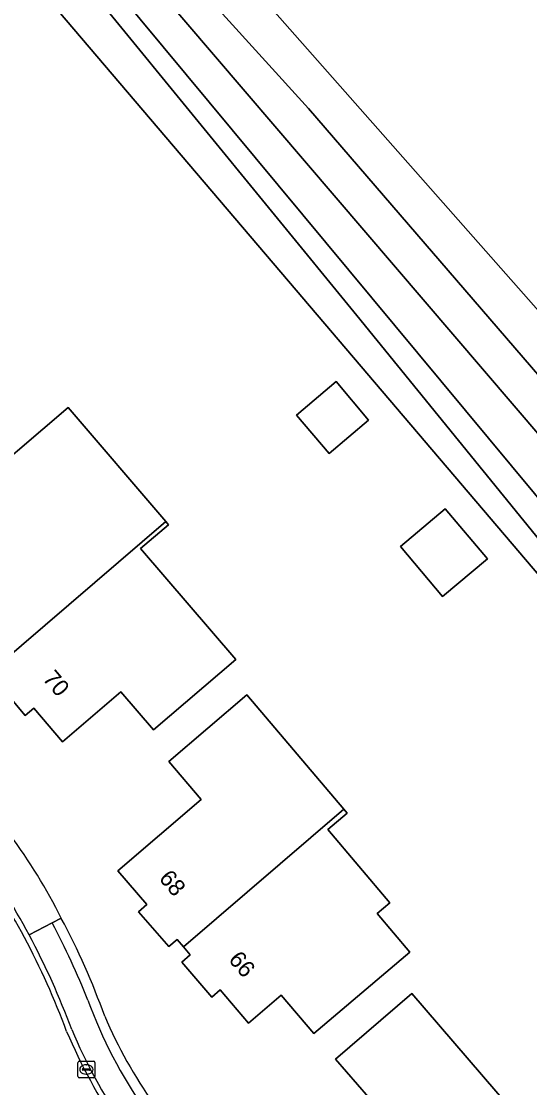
# Model space of a CAD drawing. Extents: x 164148 to 165261, y 382513 to 383432.
# Drawn here: x 164586 to 164616.4, y 383245.5 to 383309.2 of the extents above; entities that cross this region are included whole.
import ezdxf

# ---------------------------------------------------------------- set-up
doc = ezdxf.new("R2010")
doc.units = 0
for name, color, linetype in [('IMGEO_Erf', 7, 'Continuous'), ('IMGEO_Groenvoorziening', 7, 'Continuous'), ('IMGEO_Hek', 7, 'Continuous'), ('IMGEO_Kolk', 7, 'Continuous'), ('IMGEO_Oever', 7, 'Continuous'), ('IMGEO_Pand', 7, 'Continuous'), ('IMGEO_Pand_nummerreeks', 7, 'Continuous'), ('IMGEO_Parkeervlak_open', 7, 'Continuous'), ('IMGEO_Rijbaan_lokaal_open', 7, 'Continuous'), ('IMGEO_Voetpad_open', 7, 'Continuous'), ('IMGEO_Waterloop', 7, 'Continuous')]:
    doc.layers.add(name, color=color, linetype=linetype)

msp = doc.modelspace()

# ---------------------------------------------------------------- linework, layer by layer
at = {"layer": 'IMGEO_Erf'}
for points in [[(164601.938, 383293.634), (164580.845, 383318.389), (164573.491, 383327.02), (164568.932, 383331.938), (164563.693, 383332.71), (164545.833, 383335.341), (164545.779, 383334.975), (164544.24, 383324.617), (164544.174, 383323.62), (164543.739, 383320.602), (164543.186, 383316.778)], [(164608.532, 383221.856), (164626.392, 383219.249), (164626.412, 383219.679), (164643.122, 383217.367), (164643.541, 383216.874), (164670.853, 383212.753), (164601.938, 383293.634)]]:
    msp.add_lwpolyline(points, dxfattribs=at)
for points in [[(164602.427, 383285.636), (164604.797, 383287.636), (164606.739, 383285.334), (164604.37, 383283.334)], [(164588.439, 383266.118), (164586.724, 383268.118), (164586.214, 383267.684), (164584.449, 383269.761), (164584.944, 383270.195), (164584.546, 383270.661), (164580.662, 383275.211), (164584.498, 383278.504), (164582.553, 383280.79), (164588.787, 383286.094), (164594.61, 383279.268), (164594.769, 383279.082), (164593.111, 383277.661), (164598.792, 383271.032), (164593.881, 383266.823), (164591.925, 383269.105)], [(164608.644, 383277.779), (164611.32, 383280.036), (164613.834, 383277.055), (164611.159, 383274.798)], [(164596.733, 383262.658), (164594.786, 383264.941), (164599.46, 383268.922), (164605.246, 383262.094), (164605.456, 383261.846), (164604.303, 383260.868), (164608.005, 383256.499), (164607.242, 383255.853), (164609.195, 383253.548), (164603.454, 383248.683), (164601.512, 383250.975), (164599.563, 383249.311), (164597.864, 383251.294), (164597.363, 383250.864), (164595.568, 383252.954), (164596.073, 383253.387), (164595.668, 383253.869), (164595.297, 383254.309), (164594.798, 383253.877), (164592.985, 383255.965), (164593.488, 383256.4), (164591.751, 383258.408)], [(164609.326, 383251.083), (164615.196, 383244.255), (164621.06, 383237.434), (164614.258, 383231.586), (164612.288, 383233.879), (164610.685, 383232.501), (164606.788, 383237.05), (164602.89, 383241.599), (164606.73, 383244.876), (164604.764, 383247.162)]]:
    msp.add_lwpolyline(points, close=True, dxfattribs=at)
for centre, radius, start, end in [((164560.668, 383241.958), 30.858, 26.17101, 37.08875), ((164549.907, 383234.978), 43.621, 19.75068, 28.16521), ((164618.687, 383261.733), 30.216, 203.42836, 214.83284)]:
    msp.add_arc(centre, radius, start, end, dxfattribs=at)
at = {"layer": 'IMGEO_Groenvoorziening'}
for points in [[(164848.313, 383017.362), (164784.146, 383095.866), (164702.351, 383195.051), (164664.499, 383237.968), (164566.122, 383349.332), (164565.67, 383345.599), (164566.484, 383345.487), (164566.305, 383344.311), (164569.232, 383342.658), (164579.791, 383329.652), (164603.14, 383303.958), (164617.977, 383286.766), (164648.404, 383251.254), (164673.485, 383220.184), (164709.708, 383176.739), (164710.441, 383175.86), (164752.593, 383124.39), (164776.716, 383094.655), (164796.852, 383070.221), (164805.188, 383059.841), (164822.836, 383038.617)], [(164669.707, 383215.37), (164653.254, 383235.189), (164619.657, 383274.842), (164606.03, 383291.593), (164586.345, 383315.663), (164565.515, 383339.104), (164565.432, 383338.555), (164564.564, 383338.667), (164564.346, 383337.178), (164563.693, 383332.71), (164568.932, 383331.938), (164573.491, 383327.02), (164580.845, 383318.389), (164601.938, 383293.634), (164670.853, 383212.753), (164643.541, 383216.874), (164639.25, 383217.382), (164639.122, 383216.472), (164666.489, 383212.417)]]:
    msp.add_lwpolyline(points, dxfattribs=at)
at = {"layer": 'IMGEO_Hek'}
msp.add_lwpolyline([(164546.01, 383335.315), (164546.486, 383335.245), (164563.693, 383332.71), (164568.932, 383331.938), (164573.491, 383327.02), (164580.845, 383318.389), (164601.938, 383293.634), (164670.853, 383212.753), (164643.541, 383216.874), (164643.122, 383217.367), (164640.381, 383220.598), (164640.269, 383220.73)], dxfattribs=at)
at = {"layer": 'IMGEO_Kolk'}
for p, q in [((164589.365, 383246.112), (164589.365, 383246.964)), ((164589.44, 383247.038), (164590.292, 383247.038)), ((164589.853, 383246.818), (164589.878, 383246.818)), ((164590.366, 383246.964), (164590.366, 383246.112)), ((164590.292, 383246.038), (164589.44, 383246.038)), ((164589.624, 383246.532), (164589.624, 383246.544)), ((164590.062, 383246.495), (164589.664, 383246.495)), ((164589.667, 383246.581), (164590.065, 383246.581)), ((164589.876, 383246.258), (164589.851, 383246.258)), ((164590.108, 383246.544), (164590.108, 383246.532))]:
    msp.add_line(p, q, dxfattribs=at)
for points in [[(164589.365, 383246.112), (164589.365, 383246.964)], [(164589.44, 383247.038), (164590.292, 383247.038)], [(164590.366, 383246.964), (164590.366, 383246.112)], [(164590.292, 383246.038), (164589.44, 383246.038)]]:
    msp.add_lwpolyline(points, dxfattribs=at)
for centre, radius, start, end in [((164589.442, 383246.962), 0.0765, 91.55205, 178.44795), ((164589.442, 383246.962), 0.0765, 91.55205, 178.44795), ((164590.29, 383246.962), 0.0765, 1.55205, 88.44795), ((164590.29, 383246.962), 0.0765, 1.55205, 88.44795), ((164589.442, 383246.114), 0.0765, 181.55205, 268.44795), ((164589.442, 383246.114), 0.0765, 181.55205, 268.44795), ((164589.664, 383246.541), 0.0403, 85.87752, 175.75265), ((164589.661, 383246.531), 0.0366, 178.93798, 274.71019), ((164590.065, 383246.538), 0.043, 264.86636, 352.45326), ((164590.069, 383246.543), 0.0386, 1.73085, 96.63898), ((164590.29, 383246.114), 0.0765, 271.55205, 358.44795), ((164590.29, 383246.114), 0.0765, 271.55205, 358.44795)]:
    msp.add_arc(centre, radius, start, end, dxfattribs=at)
for centre, major_axis, ratio, start_param, end_param in [((164589.852, 383246.538), (-0.387, 0.002), 0.722429, 4.712389, 7.853982), ((164589.877, 383246.538), (-0.39, 0.002), 0.717154, 1.570796, 4.712389)]:
    msp.add_ellipse(centre, major_axis=major_axis, ratio=ratio, start_param=start_param, end_param=end_param, dxfattribs=at)
at = {"layer": 'IMGEO_Oever'}
msp.add_lwpolyline([(164673.485, 383220.184), (164648.404, 383251.254), (164617.977, 383286.766), (164603.14, 383303.958), (164579.791, 383329.652), (164569.232, 383342.658), (164566.305, 383344.311), (164565.515, 383339.104), (164586.345, 383315.663), (164606.03, 383291.593), (164619.657, 383274.842), (164653.254, 383235.189), (164669.707, 383215.37)], dxfattribs=at)
msp.add_lwpolyline([(164702.895, 383175.561), (164691.673, 383166.485), (164690.67, 383167.345), (164701.976, 383176.715), (164702.796, 383177.395), (164568.021, 383339.417), (164569.063, 383340.332), (164663.446, 383230.119), (164829.318, 383027.736), (164900.978, 382938.587), (164899.829, 382937.694), (164835.51, 383016.034), (164740.957, 383131.523), (164703.749, 383176.252)], close=True, dxfattribs=at)
at = {"layer": 'IMGEO_Pand'}
for points in [[(164602.427, 383285.636), (164604.37, 383283.334), (164606.739, 383285.334), (164604.797, 383287.636)], [(164594.61, 383279.268), (164588.787, 383286.094), (164582.553, 383280.79), (164584.498, 383278.504), (164580.662, 383275.211), (164584.546, 383270.661)], [(164611.159, 383274.798), (164613.834, 383277.055), (164611.32, 383280.036), (164608.644, 383277.779)], [(164594.61, 383279.268), (164584.546, 383270.661), (164584.944, 383270.195), (164584.449, 383269.761), (164586.214, 383267.684), (164586.724, 383268.118), (164588.439, 383266.118), (164591.925, 383269.105), (164593.881, 383266.823), (164598.792, 383271.032), (164593.111, 383277.661), (164594.769, 383279.082)], [(164605.246, 383262.094), (164599.46, 383268.922), (164594.786, 383264.941), (164596.733, 383262.658), (164591.751, 383258.408), (164593.488, 383256.4), (164592.985, 383255.965), (164594.798, 383253.877), (164595.297, 383254.309), (164595.668, 383253.869)], [(164605.456, 383261.846), (164605.246, 383262.094), (164595.668, 383253.869), (164596.073, 383253.387), (164595.568, 383252.954), (164597.363, 383250.864), (164597.864, 383251.294), (164599.563, 383249.311), (164601.512, 383250.975), (164603.454, 383248.683), (164609.195, 383253.548), (164607.242, 383255.853), (164608.005, 383256.499), (164604.303, 383260.868)], [(164615.196, 383244.255), (164609.326, 383251.083), (164604.764, 383247.162), (164606.73, 383244.876), (164602.89, 383241.599), (164606.788, 383237.05)]]:
    msp.add_lwpolyline(points, close=True, dxfattribs=at)
at = {"layer": 'IMGEO_Parkeervlak_open'}
msp.add_lwpolyline([(164587.824, 383255.291), (164586.442, 383254.579)], dxfattribs=at)
for centre, radius, start, end in [((164544.824, 383232.569), 48.634, 21.873, 27.8524), ((164546.883, 383233.377), 44.883, 20.25858, 28.18934), ((164616.692, 383260.435), 28.457, 200.03082, 214.95106), ((164621.229, 383262.71), 35.067, 203.16066, 213.67752)]:
    msp.add_arc(centre, radius, start, end, dxfattribs=at)
at = {"layer": 'IMGEO_Rijbaan_lokaal_open'}
for centre, radius, start, end in [((164546.508, 383233.169), 44.989, 28.19734, 35.74988), ((164546.508, 383233.169), 44.989, 28.19734, 35.74988), ((164546.932, 383233.43), 44.814, 28.15953, 35.79629), ((164546.929, 383233.398), 44.51, 20.2536, 28.19426), ((164546.929, 383233.398), 44.51, 20.2536, 28.19426), ((164546.883, 383233.377), 44.883, 20.25858, 28.18934), ((164621.29, 383262.739), 35.455, 203.14006, 213.66316), ((164621.29, 383262.739), 35.455, 203.14006, 213.66316), ((164621.229, 383262.71), 35.067, 203.16066, 213.67752)]:
    msp.add_arc(centre, radius, start, end, dxfattribs=at)
at = {"layer": 'IMGEO_Voetpad_open'}
for points in [[(164586.442, 383254.579), (164587.824, 383255.291), (164588.363, 383255.568)], [(164588.363, 383255.568), (164587.824, 383255.291)]]:
    msp.add_lwpolyline(points, dxfattribs=at)
for centre, radius, start, end in [((164560.668, 383241.958), 30.858, 26.17101, 37.08875), ((164546.932, 383233.43), 44.814, 28.15953, 35.79629), ((164549.907, 383234.978), 43.621, 19.75068, 28.16521), ((164544.824, 383232.569), 48.634, 21.873, 27.8524), ((164616.692, 383260.435), 28.457, 200.03082, 214.95106), ((164618.687, 383261.733), 30.216, 203.42836, 214.83284)]:
    msp.add_arc(centre, radius, start, end, dxfattribs=at)
at = {"layer": 'IMGEO_Waterloop'}
msp.add_lwpolyline([(164663.446, 383230.119), (164569.063, 383340.332), (164568.021, 383339.417), (164702.796, 383177.395), (164701.976, 383176.715), (164690.67, 383167.345), (164691.673, 383166.485), (164702.895, 383175.561), (164703.749, 383176.252), (164740.957, 383131.523), (164835.51, 383016.034), (164899.829, 382937.694), (164900.978, 382938.587), (164829.318, 383027.736)], close=True, dxfattribs=at)

# ---------------------------------------------------------------- texts
at = {"layer": 'IMGEO_Pand_nummerreeks'}
for s, rotation, p in [('70', 310.41623, (164587.209, 383269.861)), ('68', 310.6626, (164594.155, 383257.926)), ('66', 310.39331, (164598.315, 383253.077))]:
    msp.add_text(s, height=1, rotation=rotation, dxfattribs=at).set_placement(p)

doc.saveas('drawing.dxf')
